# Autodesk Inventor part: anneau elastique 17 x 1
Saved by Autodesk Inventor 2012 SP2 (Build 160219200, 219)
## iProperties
Created: 2013-04
Part Number: anneau elastique 17 x 1
Material: Default
Document SubType Name: Modeling
Designer: papa
Density: 1 g/cm^3
Mass: 0.107405 g
Surface Area: 3.48992 cm^2
Volume: 0.107405 cm^3
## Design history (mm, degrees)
node "anneau elastique 17 x 11"
node "anneau elastique 17 x 1"
node "Base1"
